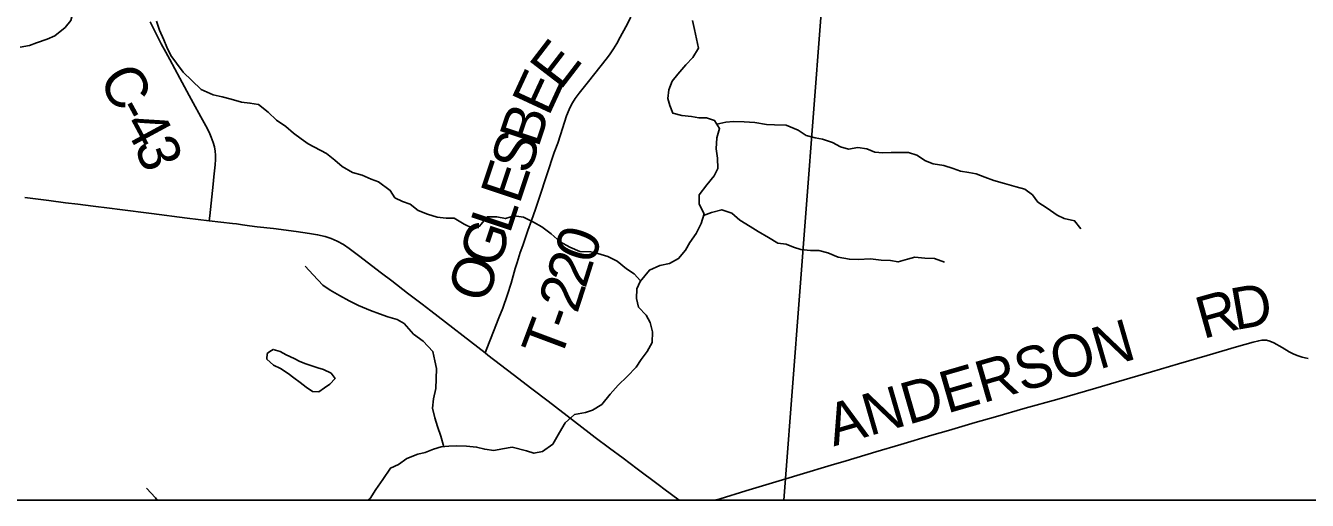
# Model space of a CAD drawing. Extents: x -1.4 to 35.4, y 0 to 22.
# Drawn here: x 6.307 to 8.05, y 13.055 to 13.699 of the extents above; entities that cross this region are included whole.
import ezdxf

# ---------------------------------------------------------------- set-up
doc = ezdxf.new("R2010")
doc.units = 0
for name, color, linetype in [('Default', 7, 'Continuous'), ('GM_X_County_Road', 7, 'Continuous'), ('GM_X_County_Road_Text', 7, 'Continuous'), ('GM_X_Minor_Lake', 7, 'Continuous'), ('GM_X_Minor_River', 7, 'Continuous'), ('GM_X_State_Route', 7, 'Continuous'), ('GM_X_Township_Road', 7, 'Continuous'), ('GM_X_Township_Road_Text', 7, 'Continuous'), ('SC_Scratch1', 7, 'Continuous'), ('SH_Border', 7, 'Continuous'), ('SH_Cut_Line', 7, 'Continuous')]:
    doc.layers.add(name, color=color, linetype=linetype)

msp = doc.modelspace()

# ---------------------------------------------------------------- linework, layer by layer
at = {"layer": 'Default'}
msp.add_lwpolyline([(2.6843, 17.0961), (2.6688, 16.9164), (2.6641, 16.8609), (2.4708, 14.7557), (2.4607, 14.5392), (2.3914, 13.7798), (2.3288, 13.0546), (7.3379, 13.0546), (7.34, 13.0844), (7.3971, 13.8291), (7.4835, 14.4701), (7.5226, 14.9278), (7.5248, 14.9516), (7.5275, 14.9811), (7.5875, 15.692), (7.6066, 15.899), (7.693, 16.8959), (7.7561, 17.6322)], dxfattribs=at)
msp.add_lwpolyline([(7.3379, 13.0546), (9, 13.0546), (9, 15.5849), (8.9658, 15.5879), (8.256, 15.6481), (8.1578, 15.6562), (7.5875, 15.692), (7.5275, 14.9811), (7.5248, 14.9516), (7.5226, 14.9278), (7.4835, 14.4701), (7.3971, 13.8291), (7.34, 13.0844)], close=True, dxfattribs=at)
at = {"layer": 'GM_X_County_Road'}
msp.add_lwpolyline([(6.5564, 13.4345), (6.5571, 13.4411), (6.5617, 13.4843), (6.5629, 13.4942), (6.5647, 13.5102), (6.5652, 13.5177), (6.5651, 13.5234), (6.5646, 13.5291), (6.5636, 13.5346), (6.5619, 13.5407), (6.5593, 13.5478), (6.5563, 13.5546), (6.5518, 13.5635), (6.5452, 13.5755), (6.5347, 13.5944), (6.529, 13.6047), (6.5163, 13.6282), (6.5096, 13.6408), (6.5028, 13.6534), (6.4975, 13.6633), (6.4913, 13.6747), (6.4824, 13.6918), (6.4761, 13.7046)], dxfattribs=at)
at = {"layer": 'GM_X_Minor_Lake'}
for points in [[(6.639, 13.2566), (6.6352, 13.254), (6.635, 13.2464), (6.644, 13.2382), (6.6533, 13.2335), (6.6638, 13.2269), (6.6716, 13.221), (6.6799, 13.2148), (6.6881, 13.2082), (6.697, 13.2023), (6.7057, 13.2021), (6.713, 13.2073)], [(6.713, 13.2073), (6.7203, 13.2125), (6.7277, 13.2199), (6.7222, 13.2272), (6.7117, 13.2324), (6.7041, 13.2344), (6.6962, 13.2372), (6.6879, 13.24), (6.6797, 13.2432), (6.6718, 13.2472), (6.6613, 13.2523), (6.6527, 13.257), (6.6433, 13.2595), (6.639, 13.2566)]]:
    msp.add_lwpolyline(points, dxfattribs=at)
at = {"layer": 'GM_X_Minor_River'}
for points in [[(6.4801, 13.7259), (6.4709, 13.7379), (6.4593, 13.748), (6.4462, 13.7558), (6.4364, 13.7583), (6.4228, 13.7586), (6.4112, 13.7501), (6.3964, 13.7477), (6.3845, 13.7392), (6.3816, 13.7264), (6.3712, 13.7163), (6.3683, 13.7065), (6.3605, 13.6968), (6.3467, 13.6857), (6.336, 13.681), (6.3218, 13.676), (6.3123, 13.6724), (6.2994, 13.6703)], [(7.1429, 13.3528), (7.1341, 13.3625), (7.124, 13.3691), (7.111, 13.3796), (7.0986, 13.3859), (7.085, 13.39), (7.0752, 13.3921), (7.0605, 13.3928), (7.0466, 13.3987), (7.0338, 13.4058), (7.0212, 13.4167), (7.0089, 13.426), (6.9973, 13.4327), (6.9838, 13.4394), (6.9709, 13.4412), (6.9591, 13.4373), (6.9474, 13.4398), (6.9345, 13.4396), (6.924, 13.4269), (6.9145, 13.4245), (6.9032, 13.4296), (6.8894, 13.4379), (6.8788, 13.4377), (6.8663, 13.4391), (6.8531, 13.4435), (6.8407, 13.4483), (6.8299, 13.4569), (6.8194, 13.4605), (6.8089, 13.4656), (6.8026, 13.4756), (6.7866, 13.4873), (6.7768, 13.4909), (6.7644, 13.4965), (6.7512, 13.4998), (6.7374, 13.508), (6.7273, 13.5166), (6.7158, 13.5259), (6.6911, 13.5389), (6.6813, 13.5456), (6.6709, 13.5533), (6.6605, 13.5623), (6.6481, 13.5709), (6.6366, 13.5821), (6.6236, 13.5922), (6.6119, 13.5943), (6.6002, 13.5953), (6.5862, 13.5994), (6.5742, 13.6027), (6.5617, 13.6056), (6.5456, 13.6127), (6.5326, 13.6251), (6.5211, 13.6364), (6.5118, 13.6483), (6.5041, 13.6591), (6.4986, 13.6702), (6.4947, 13.6801), (6.4889, 13.6931), (6.4846, 13.7057)], [(7.2459, 13.5321), (7.2466, 13.5469), (7.2503, 13.5597), (7.2437, 13.5708), (7.2328, 13.5741), (7.2222, 13.5743), (7.2123, 13.576), (7.1991, 13.5774), (7.1867, 13.5807), (7.1827, 13.591), (7.1799, 13.6006), (7.1813, 13.6123), (7.186, 13.624), (7.1938, 13.6337), (7.2047, 13.6464), (7.214, 13.656), (7.2218, 13.6688), (7.2191, 13.6814), (7.2163, 13.6943), (7.2135, 13.7065)], [(7.2468, 13.5655), (7.2588, 13.5683), (7.2694, 13.5692), (7.2838, 13.5689), (7.2982, 13.5679), (7.314, 13.5653), (7.325, 13.5647), (7.3409, 13.5644), (7.3571, 13.5576), (7.3683, 13.5502), (7.3803, 13.5469), (7.3905, 13.5452), (7.4041, 13.5407), (7.4146, 13.5348), (7.4255, 13.5316), (7.4384, 13.534), (7.4505, 13.5322), (7.4614, 13.5275), (7.4723, 13.5265), (7.4837, 13.527), (7.4936, 13.5272), (7.5072, 13.5269), (7.5185, 13.5233), (7.5305, 13.5159), (7.5406, 13.5115), (7.5553, 13.5093), (7.5681, 13.5052), (7.5779, 13.5016), (7.5892, 13.4999), (7.5991, 13.4982), (7.6111, 13.4934), (7.6231, 13.489), (7.6378, 13.4849), (7.6536, 13.4804), (7.6653, 13.4775), (7.6758, 13.4694), (7.6831, 13.4597), (7.6958, 13.4515), (7.7093, 13.4421), (7.719, 13.4374), (7.733, 13.4345), (7.7415, 13.4233)], [(6.7727, 13.0546), (6.7751, 13.057), (6.7829, 13.0693), (6.7927, 13.0828), (6.8029, 13.0982), (6.8136, 13.1033), (6.8251, 13.1114), (6.84, 13.1175), (6.8503, 13.1196), (6.8613, 13.1239), (6.872, 13.1271), (6.8823, 13.1281), (6.8929, 13.1286), (6.9065, 13.128), (6.9201, 13.1269), (6.9311, 13.1241), (6.9435, 13.1223), (6.9553, 13.1247), (6.9682, 13.1267), (6.9878, 13.1218), (6.998, 13.1186), (7.0098, 13.121), (7.0236, 13.131), (7.0327, 13.1467), (7.0405, 13.1598), (7.0533, 13.171), (7.0681, 13.1737), (7.0776, 13.1769), (7.0903, 13.185), (7.1016, 13.1988), (7.1124, 13.2112), (7.1248, 13.2227), (7.1368, 13.2357), (7.1438, 13.2458), (7.152, 13.257), (7.1587, 13.269), (7.1594, 13.2834), (7.1562, 13.2964), (7.1504, 13.306), (7.14, 13.3172), (7.1376, 13.3286), (7.1378, 13.3419), (7.1422, 13.3521), (7.155, 13.3674), (7.1692, 13.3735), (7.1821, 13.3763), (7.1947, 13.3829), (7.2041, 13.3945), (7.21, 13.405), (7.2186, 13.4169), (7.2253, 13.4308), (7.2293, 13.444), (7.2228, 13.4571), (7.2227, 13.4696), (7.2332, 13.483), (7.2429, 13.4954), (7.248, 13.5055), (7.2476, 13.5196), (7.2459, 13.5321)], [(7.2286, 13.4416), (7.2392, 13.4454), (7.2533, 13.4493), (7.2669, 13.4448), (7.278, 13.4351), (7.2922, 13.4265), (7.3027, 13.4198), (7.3169, 13.4116), (7.3297, 13.4041), (7.341, 13.4024), (7.3511, 13.3984), (7.3609, 13.3955), (7.3742, 13.3941), (7.3855, 13.3939), (7.3976, 13.3906), (7.4115, 13.3851), (7.427, 13.3821), (7.4387, 13.3819), (7.4554, 13.3827), (7.4701, 13.3809), (7.483, 13.3802), (7.4932, 13.3785), (7.5061, 13.3824), (7.516, 13.3849), (7.5293, 13.3835), (7.5425, 13.3832), (7.5561, 13.378)], [(6.8753, 13.1274), (6.8716, 13.1416), (6.8669, 13.1549), (6.8634, 13.1668), (6.8602, 13.1797), (6.8616, 13.1926), (6.8646, 13.2066), (6.8652, 13.2198), (6.8655, 13.2335), (6.8634, 13.2442), (6.8603, 13.2567), (6.8473, 13.271), (6.8343, 13.2804), (6.8217, 13.2947), (6.8119, 13.3002), (6.7995, 13.3038), (6.7878, 13.3079), (6.7758, 13.3123), (6.7593, 13.3194), (6.7469, 13.3257), (6.7334, 13.3328), (6.7207, 13.3399), (6.711, 13.3469), (6.6976, 13.3609), (6.6869, 13.3725)], [(6.4857, 13.0546), (6.4834, 13.0582), (6.4712, 13.0713)]]:
    msp.add_lwpolyline(points, dxfattribs=at)
at = {"layer": 'GM_X_State_Route'}
msp.add_lwpolyline([(6.3056, 13.4659), (6.3382, 13.4617), (6.3611, 13.4589), (6.3777, 13.4568), (6.3986, 13.4541), (6.4208, 13.4514), (6.435, 13.4496), (6.4782, 13.4441), (6.5263, 13.4381), (6.5564, 13.4345), (6.5879, 13.4306), (6.5935, 13.43), (6.6015, 13.4288), (6.6113, 13.4277), (6.6218, 13.4263), (6.644, 13.4238), (6.6748, 13.4198), (6.6927, 13.4172), (6.7038, 13.4154), (6.7142, 13.4128), (6.7221, 13.4103), (6.7303, 13.4067), (6.7389, 13.402), (6.7469, 13.3968), (6.7595, 13.3874), (6.7907, 13.3632), (6.8046, 13.3527), (6.8262, 13.336), (6.8459, 13.3209), (6.8577, 13.3118), (6.9316, 13.2549), (6.9354, 13.2519), (6.9699, 13.2254), (6.9951, 13.2062), (7.0174, 13.1892), (7.0532, 13.1615), (7.0729, 13.1463), (7.0813, 13.1399), (7.1007, 13.1254), (7.1191, 13.1117), (7.1384, 13.0972), (7.1667, 13.0761), (7.1686, 13.0746), (7.1745, 13.0701), (7.1953, 13.0546)], dxfattribs=at)
at = {"layer": 'GM_X_Township_Road'}
for points in [[(6.9316, 13.2549), (6.934, 13.2609), (6.9432, 13.284), (6.9504, 13.3023), (6.9555, 13.3155), (6.9621, 13.334), (6.9669, 13.3494), (6.9726, 13.3697), (6.9751, 13.3778), (6.9793, 13.3911), (6.9827, 13.401), (6.9872, 13.4144), (6.9897, 13.4213), (6.9947, 13.4349), (6.9999, 13.4501), (7.0056, 13.4665), (7.0257, 13.527), (7.0303, 13.5398), (7.0342, 13.5509), (7.0394, 13.5681), (7.0424, 13.577), (7.0458, 13.5857), (7.0476, 13.5897), (7.0504, 13.5947), (7.0541, 13.6005), (7.0593, 13.6075), (7.0721, 13.6236), (7.0876, 13.643), (7.098, 13.6561), (7.1016, 13.6611), (7.1061, 13.6678), (7.1108, 13.675), (7.1153, 13.6837), (7.1228, 13.698), (7.1299, 13.7111)], [(7.3403, 13.0839), (7.3598, 13.0898), (7.4021, 13.1024), (7.4224, 13.1083), (7.4629, 13.1204), (7.4968, 13.1304), (7.5391, 13.143), (7.5618, 13.1496), (7.5981, 13.1604), (7.6256, 13.1682), (7.6657, 13.1797), (7.7088, 13.1916), (7.7619, 13.207), (7.7894, 13.2149), (7.8376, 13.2292), (7.8746, 13.24), (7.9134, 13.2513), (7.9534, 13.263), (7.9761, 13.2695), (7.9834, 13.2713), (7.9878, 13.272), (7.991, 13.2722), (7.9942, 13.272), (7.9986, 13.2709), (8.0038, 13.2686), (8.0152, 13.2621), (8.0248, 13.2565), (8.0314, 13.2532), (8.0371, 13.2508), (8.0424, 13.2491), (8.0465, 13.2481), (8.0507, 13.2474)], [(7.2437, 13.0546), (7.251, 13.0567), (7.2861, 13.0673), (7.3271, 13.0798), (7.3403, 13.0839)]]:
    msp.add_lwpolyline(points, dxfattribs=at)
at = {"layer": 'SC_Scratch1'}
msp.add_line((-1.4282, 13.0546), (35.3749, 13.0546), dxfattribs=at)
at = {"layer": 'SH_Border'}
msp.add_lwpolyline([(9, 19.8546), (2.2, 19.8546), (2.2, 13.0546), (9, 13.0546)], close=True, dxfattribs=at)
at = {"layer": 'SH_Cut_Line'}
msp.add_lwpolyline([(2.6843, 17.0961), (2.6688, 16.9164), (2.6641, 16.8609), (2.4708, 14.7557), (2.4607, 14.5392), (2.3914, 13.7798), (2.3288, 13.0546), (9, 13.0546), (9, 18.9633)], dxfattribs=at)

# ---------------------------------------------------------------- texts
at = {"layer": 'GM_X_County_Road_Text'}
for s, rotation, p in [('C', 298.4312, (6.4052, 13.6275)), ('-', 298.412, (6.4274, 13.5864)), ('4', 298.3598, (6.4385, 13.5659)), ('3', 289.8982, (6.4543, 13.5371))]:
    msp.add_text(s, height=0.0568, rotation=rotation, dxfattribs=at).set_placement(p)
at = {"layer": 'GM_X_Township_Road_Text'}
for s, height, rotation, p in [('E', 0.0568, 52.4701, (7.034, 13.6107)), ('E', 0.0568, 65.1563, (7.0179, 13.575)), ('B', 0.0568, 71.4626, (7.0037, 13.5323)), ('S', 0.0568, 71.6199, (6.9916, 13.496)), ('E', 0.0568, 71.6172, (6.9782, 13.4556)), ('L', 0.0568, 71.6192, (6.9648, 13.4153)), ('G', 0.0568, 71.618, (6.949, 13.3679)), ('0', 0.0568, 71.1775, (7.0782, 13.374)), ('O', 0.0568, 71.618, (6.9332, 13.3204)), ('2', 0.0568, 72.4698, (7.0677, 13.341)), ('2', 0.0568, 71.9823, (7.0567, 13.3072)), ('R', 0.0568, 15.6012, (7.9077, 13.2735)), ('D', 0.0568, 9.9363, (7.9512, 13.2857)), ('T', 0.0568, 69.4259, (7.0331, 13.2428)), ('-', 0.0568, 70.468, (7.0484, 13.2836)), ('ANDERSON', 0.05682, 16.1507, (7.4055, 13.1277))]:
    msp.add_text(s, height=height, rotation=rotation, dxfattribs=at).set_placement(p)

doc.saveas('drawing.dxf')
